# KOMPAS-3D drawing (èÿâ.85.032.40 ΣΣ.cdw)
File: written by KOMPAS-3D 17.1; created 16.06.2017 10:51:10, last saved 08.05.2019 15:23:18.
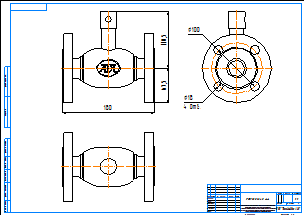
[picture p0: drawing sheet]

Sheet 1: A2, landscape

Title block, sheet 1: name: КШГ.85.032.40 фф; material: Внимание! Данный продукт является объектом авторского права ООО «Торговый Дом АДЛ». / Запрещается изменение, копирование, распространение / (в том числе путем копирования на другие сайты и ресурсы в Интернете) / или любое иное использование информации и объектов без предварительного / согласия правообладателя (ООО «Торговый Дом АДЛ»).; scale: 1:1; sheets: 1; organisation: ООО "Торговый дом АДЛ"; sheet format: A2; stored path: C:\Users\tra\Desktop\2д чертежи\Шаровые краны БИВАЛ\КШ_Бивал_серия_82_85\KOMPAS 2D\КШГ.85.032.40 фф.cdw

Views: Спереди 1, Проекционный вид 2, Проекционный вид 3
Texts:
  Klimkovich
  ADL
Dimensions and other numbers on the sheet: 180; 110,5; 67,5; 100; 18; 4 Отв.; 1:1; 1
